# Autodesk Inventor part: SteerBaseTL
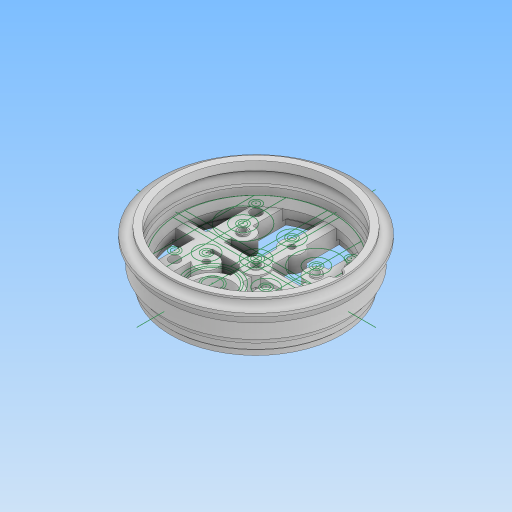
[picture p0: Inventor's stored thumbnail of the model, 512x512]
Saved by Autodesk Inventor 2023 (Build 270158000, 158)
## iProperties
Created: 2024-05
Part Number: SteerBaseTL
Material: 一般
Document SubType Name: Modeling
Designer: kumagai
Density: 1 g/cm^3
Appearance: 既定
Author: kumagai
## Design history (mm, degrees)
derived "SteerBase.ipt"
  sketch "スケッチ5"
    geometry: L1 (0, -60.2)-(0, 60.2) reference; L2 (-60.2, 0)-(60.2, 0) reference; L3 (-19, 34.059)-(-19, -34.059) reference; L4 (-28, 27.148)-(-28, -27.148) reference; L5 (-3, 38.884)-(-3, 34.135) reference; L6 (-3, 9.865)-(-3, -38.884) reference; L7 (3, 38.884)-(3, 34.135) reference; L8 (3, 9.865)-(3, -38.884) reference; L9 (28, 27.148)-(28, -27.148) reference; L10 (19, 34.059)-(19, -34.059) reference; L11 (-38.884, 3)-(38.884, 3) reference; L12 (-38.884, -3)-(38.884, -3) reference; C1 r 11 at (0, 22) reference; C2 r 10 at (0, 22) reference; C3 r 4.9 at (0, 22) reference; C4 r 4 at (0, 22) reference; C5 r 1.65 at (-15, 10) reference; C6 r 1.65 at (15, 10) reference; C7 r 1.65 at (0, -18) reference; C8 r 11 at (-18.508, -11.894) reference; C9 r 11 at (18.508, -11.894) reference; C10 r 1.65 at (-18.508, -11.894) reference; C11 r 1.65 at (18.508, -11.894) reference; C12 r 5.5 at (-18.508, -11.894) reference; C13 r 5.5 at (0, -18) reference; C14 r 5.5 at (18.508, -11.894) reference; C15 r 5.5 at (-15, 10) reference; C16 r 5.5 at (15, 10) reference; C17 r 2.65 at (-15, 10) reference; C18 r 2.65 at (-18.508, -11.894) reference; C19 r 2.65 at (0, -18) reference; C20 r 2.65 at (18.508, -11.894) reference; C21 r 2.65 at (15, 10) reference; C22 r 43 at (0, 0) reference; C23 r 42 at (0, 0) reference; C24 r 6 at (0, 0) reference; C25 r 2 at (0, 0) reference; C26 r 3 at (0, 0) reference; C27 r 1.65 at (24, 17) reference; C28 r 1.65 at (-24, 17) reference; C29 r 1.65 at (24, -24) reference; C30 r 1.65 at (-24, -24) reference; C31 r 2.65 at (24, -24) reference; C32 r 2.65 at (24, 17) reference; C33 r 2.65 at (-24, -24) reference; C34 r 2.65 at (-24, 17) reference; A1 r 12.5 centre (0, 22) between (-3, 34.135) and (-3, 9.865) reference; 14 further points
    constraints: 1 other
node "作業平面1"
sketch "スケッチ2"
  geometry: L1 (19, 3)-(19, 6.225) reference; L2 (19, 13.775)-(19, 34.059) reference; L3 (3, 38.884)-(3, 34.135) reference; L4 (3, 9.865)-(3, 3) reference; L5 (3, 3)-(19, 3) reference; L6 (38.884, -3)-(28, -3) reference; L7 (28, -3)-(28, -27.148) reference; L8 (28, 3)-(38.884, 3) reference; L9 (28, 27.148)-(28, 3) reference; L10 (-38.884, 3)-(-28, 3) reference; L11 (-28, 3)-(-28, 27.148) reference; L12 (-28, -3)-(-38.884, -3) reference; L13 (-28, -27.148)-(-28, -3) reference; L14 (3, -22.61)-(3, -38.884) reference; L15 (19, -34.059)-(19, -17.372) reference; L16 (19, -6.416)-(19, -3) reference; L17 (19, -3)-(3, -3) reference; L18 (3, -3)-(3, -13.39) reference; L19 (-19, 3)-(-3, 3) reference; L20 (-3, 3)-(-3, 9.865) reference; L21 (-3, 34.135)-(-3, 38.884) reference; L22 (-19, 34.059)-(-19, 13.775) reference; L23 (-19, 6.225)-(-19, 3) reference; L24 (-19, -17.372)-(-19, -34.059) reference; L25 (-3, -38.884)-(-3, -22.61) reference; L26 (-3, -13.39)-(-3, -3) reference; L27 (-3, -3)-(-19, -3) reference; L28 (-19, -3)-(-19, -6.416) reference; C1 r 2 at (0, 0) reference; C2 r 2.65 at (-15, 10) reference; C3 r 2.65 at (-18.508, -11.894) reference; C4 r 2.65 at (15, 10) reference; C5 r 2.65 at (0, -18) reference; C6 r 2.65 at (18.508, -11.894) reference; C7 r 1.65 at (24, 17) reference; C8 r 1.65 at (-24, 17) reference; C9 r 1.65 at (24, -24) reference; C10 r 1.65 at (-24, -24) reference; C11 r 4 at (0, 22) reference; C12 r 43 at (0, 0) reference; C13 r 37.5 at (0, 0) reference; C14 r 6 at (0, 0) reference; A1 r 5.5 centre (15, 10) between (19, 13.775) and (19, 6.225) reference; A2 r 39 centre (0, 0) between (19, 34.059) and (3, 38.884) reference; A3 r 12.5 centre (0, 22) between (3, 9.865) and (3, 34.135) reference; A4 r 39 centre (0, 0) between (28, -27.148) and (38.884, -3) reference; A5 r 39 centre (0, 0) between (38.884, 3) and (28, 27.148) reference; A6 r 39 centre (0, 0) between (-28, 27.148) and (-38.884, 3) reference; A7 r 39 centre (0, 0) between (-38.884, -3) and (-28, -27.148) reference; A8 r 5.5 centre (0, -18) between (3, -22.61) and (3, -13.39) reference; A9 r 39 centre (0, 0) between (3, -38.884) and (19, -34.059) reference; A10 r 5.5 centre (18.508, -11.894) between (19, -6.416) and (19, -17.372) reference; A11 r 12.5 centre (0, 22) between (-3, 34.135) and (-3, 9.865) reference; A12 r 39 centre (0, 0) between (-3, 38.884) and (-19, 34.059) reference; A13 r 5.5 centre (-15, 10) between (-19, 6.225) and (-19, 13.775) reference; A14 r 5.5 centre (-18.508, -11.894) between (-19, -17.372) and (-19, -6.416) reference; A15 r 39 centre (0, 0) between (-19, -34.059) and (-3, -38.884) reference; A16 r 5.5 centre (0, -18) between (-3, -13.39) and (-3, -22.61) reference; 25 further points
extrude "押し出し1" cut sketch "スケッチ2" stored distance "d2" = 10; taper "d3" = 0 deg
feature "ソリッド1::SteerBase.ipt" dims "d0" = 10
tag "TaggingFeature1"
node "ソリッド1"
node "断面エッジを投影1"
other parameters: "d1" = -0.1
